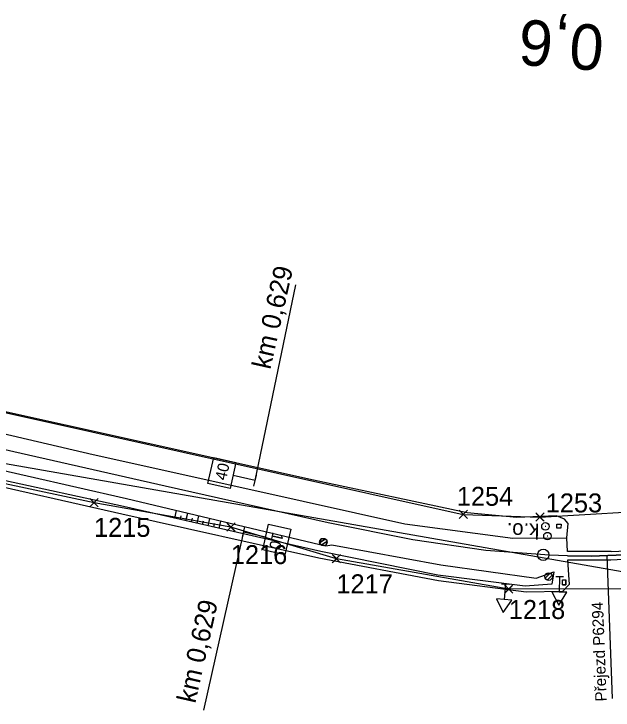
# Model space of a CAD drawing. Extents: x -738085 to -734426, y -1122197 to -1119748.
# Drawn here: x -734654.8 to -734575.8, y -1120245.5 to -1120153.7 of the extents above; entities that cross this region are included whole.
import ezdxf

# ---------------------------------------------------------------- set-up
doc = ezdxf.new("R2010")
doc.units = 0
for name, color, linetype in [('SŽDC', 7, 'Continuous'), ('Vrstva 1', 7, 'Continuous'), ('Vrstva 11', 7, 'Continuous'), ('Vrstva 12', 7, 'Continuous'), ('Vrstva 27', 7, 'Continuous'), ('Vrstva 4', 7, 'Continuous'), ('Vrstva 48', 7, 'Continuous'), ('Vrstva 49', 7, 'Continuous'), ('Vrstva 5', 7, 'Continuous'), ('Vrstva 51', 7, 'Continuous'), ('Vrstva 60', 7, 'Continuous'), ('Vrstva 63', 7, 'Continuous'), ('Vrstva 7', 7, 'Continuous')]:
    doc.layers.add(name, color=color, linetype=linetype)

msp = doc.modelspace()

# ---------------------------------------------------------------- linework, layer by layer
at = {"layer": 'SŽDC'}
for p, q in [((-734676.02, -1120201.83), (-734595.59, -1120219.69)), ((-734626.24, -1120221.38), (-734644.28, -1120218.16)), ((-734585.49, -1120220.06), (-734570.35, -1120219.16)), ((-734595.59, -1120219.69), (-734585.49, -1120220.06)), ((-734612.32, -1120225.54), (-734626.24, -1120221.38)), ((-734589.59, -1120229.56), (-734612.32, -1120225.54)), ((-734562.36, -1120229.51), (-734589.59, -1120229.56))]:
    msp.add_line(p, q, dxfattribs=at)
msp.add_lwpolyline([(-734644.28, -1120218.16), (-734672.9, -1120212.048), (-734681.74, -1120210.16)], dxfattribs=at)
at = {"layer": 'Vrstva 1'}
for points in [[(-734613.421, -1120220.79), (-734634.887, -1120215.956), (-734653.902, -1120211.657), (-734667.211, -1120208.647), (-734679.781, -1120205.8), (-734683.652, -1120204.918), (-734685.399, -1120204.523), (-734700.124, -1120201.196), (-734707.734, -1120199.476), (-734730.994, -1120194.203), (-734759.473, -1120187.753), (-734794.897, -1120179.749), (-734825.419, -1120172.844), (-734846.465, -1120168.091), (-734858.476, -1120165.343)], [(-734613.421, -1120220.79), (-734634.887, -1120215.956), (-734653.902, -1120211.657), (-734667.211, -1120208.647), (-734679.781, -1120205.8), (-734683.652, -1120204.918), (-734685.399, -1120204.523), (-734700.124, -1120201.196), (-734707.734, -1120199.476), (-734730.994, -1120194.203), (-734759.473, -1120187.753), (-734794.897, -1120179.749), (-734825.419, -1120172.844), (-734846.465, -1120168.091), (-734858.476, -1120165.343)], [(-734571.046, -1120224.919), (-734578.724, -1120225.209), (-734581.845, -1120225.143), (-734584.227, -1120225.092), (-734592.616, -1120224.456), (-734602.238, -1120223.05), (-734613.421, -1120220.79)], [(-734571.046, -1120224.919), (-734578.724, -1120225.209), (-734581.845, -1120225.143), (-734584.227, -1120225.092), (-734592.616, -1120224.456), (-734602.238, -1120223.05), (-734613.421, -1120220.79)]]:
    msp.add_lwpolyline(points, dxfattribs=at)
at = {"layer": 'Vrstva 11'}
for p, q in [((-734613.741, -1120222.96), (-734614.524, -1120223.455)), ((-734613.547, -1120223.281), (-734614.319, -1120223.769)), ((-734584.129, -1120227.449), (-734584.798, -1120228.09)), ((-734583.875, -1120227.725), (-734584.535, -1120228.357))]:
    msp.add_line(p, q, dxfattribs=at)
for centre in [(-734614.037, -1120223.359), (-734584.34, -1120227.899)]:
    msp.add_circle(centre, 0.5, dxfattribs=at)
at = {"layer": 'Vrstva 12'}
for p, q in [((-734613.724, -1120223.83), (-734614.508, -1120223.672)), ((-734582.533, -1120228.971), (-734582.083, -1120228.971))]:
    msp.add_line(p, q, dxfattribs=at)
for points in [[(-734582.722, -1120221.527), (-734583.272, -1120221.515), (-734583.26, -1120220.965), (-734582.71, -1120220.977), (-734582.722, -1120221.527)], [(-734614.35, -1120222.888), (-734613.566, -1120223.046), (-734613.724, -1120223.83), (-734614.508, -1120223.672), (-734614.35, -1120222.888)], [(-734614.35, -1120222.888), (-734614.508, -1120223.672), (-734614.508, -1120223.672)], [(-734613.566, -1120223.046), (-734613.724, -1120223.83), (-734613.724, -1120223.83)], [(-734582.533, -1120228.321), (-734582.083, -1120228.321), (-734582.083, -1120228.971), (-734582.533, -1120228.971), (-734582.533, -1120228.321)], [(-734582.533, -1120228.321), (-734582.533, -1120228.321), (-734582.083, -1120228.321), (-734582.083, -1120228.321)], [(-734582.533, -1120228.971), (-734582.533, -1120228.971), (-734582.533, -1120228.321)], [(-734582.083, -1120228.971), (-734582.083, -1120228.971), (-734582.083, -1120228.321)]]:
    msp.add_lwpolyline(points, dxfattribs=at)
at = {"layer": 'Vrstva 27'}
msp.add_line((-734584.441, -1120222.566), (-734584.541, -1120222.564), dxfattribs=at)
msp.add_circle((-734584.491, -1120222.565), 0.5, dxfattribs=at)
at = {"layer": 'Vrstva 4'}
msp.add_line((-734575.9, -1120244.003), (-734576.613, -1120225.129), dxfattribs=at)
for points in [[(-734685.169, -1120203.528), (-734684.555, -1120202.999), (-734671.173, -1120205.544), (-734644.385, -1120211.815), (-734623.222, -1120216.49), (-734603.28, -1120220.93), (-734589.054, -1120222.819), (-734581.933, -1120222.775)], [(-734581.845, -1120225.143), (-734578.724, -1120225.209), (-734571.046, -1120224.919)]]:
    msp.add_lwpolyline(points, dxfattribs=at)
at = {"layer": 'Vrstva 48'}
for p, q in [((-734633.619, -1120220.212), (-734633.383, -1120219.181)), ((-734632.887, -1120220.379), (-734632.77, -1120219.867)), ((-734632.156, -1120220.546), (-734631.924, -1120219.528)), ((-734631.425, -1120220.713), (-734631.31, -1120220.207)), ((-734630.694, -1120220.88), (-734630.465, -1120219.875)), ((-734629.231, -1120221.214), (-734629.005, -1120220.222)), ((-734629.963, -1120221.047), (-734629.849, -1120220.548)), ((-734628.5, -1120221.381), (-734628.388, -1120220.888)), ((-734627.769, -1120221.548), (-734627.546, -1120220.57))]:
    msp.add_line(p, q, dxfattribs=at)
at = {"layer": 'Vrstva 49'}
for p, q in [((-734640.39, -1120218.667), (-734667.641, -1120212.759)), ((-734614.356, -1120224.609), (-734640.39, -1120218.667)), ((-734598.954, -1120227.698), (-734614.356, -1120224.609)), ((-734587.437, -1120229.178), (-734598.954, -1120227.698))]:
    msp.add_line(p, q, dxfattribs=at)
for points in [[(-734683.53, -1120207.371), (-734683.499, -1120207.692), (-734668.248, -1120211.532), (-734667.467, -1120211.708), (-734666.214, -1120211.637), (-734640.018, -1120217.602), (-734614.508, -1120223.672), (-734613.724, -1120223.83), (-734612.931, -1120223.724), (-734598.542, -1120226.335), (-734585.987, -1120228.092), (-734583.653, -1120227.271)], [(-734583.653, -1120227.271), (-734583.922, -1120228.893), (-734587.437, -1120229.178)]]:
    msp.add_lwpolyline(points, dxfattribs=at)
at = {"layer": 'Vrstva 5'}
for p, q in [((-734623.023, -1120215.234), (-734617.67, -1120189.43)), ((-734623.023, -1120215.234), (-734625.95, -1120214.575)), ((-734623.188, -1120215.966), (-734622.858, -1120214.502)), ((-734624.584, -1120222.019), (-734629.86, -1120245.51)), ((-734624.419, -1120221.287), (-734624.749, -1120222.751)), ((-734624.584, -1120222.019), (-734621.657, -1120222.678))]:
    msp.add_line(p, q, dxfattribs=at)
for points in [[(-734625.565, -1120212.868), (-734626.334, -1120216.282), (-734629.261, -1120215.623), (-734628.492, -1120212.209)], [(-734622.042, -1120224.385), (-734621.273, -1120220.971), (-734618.346, -1120221.63), (-734619.115, -1120225.044)]]:
    msp.add_lwpolyline(points, close=True, dxfattribs=at)
at = {"layer": 'Vrstva 51'}
for p, q in [((-734576.111, -1120224.576), (-734581.836, -1120224.609)), ((-734570.996, -1120225.49), (-734576.137, -1120225.727)), ((-734582.395, -1120227.955), (-734583.395, -1120227.933)), ((-734589.549, -1120228.959), (-734590.547, -1120228.883))]:
    msp.add_line(p, q, dxfattribs=at)
for points in [[(-734581.836, -1120224.609), (-734581.933, -1120222.775), (-734581.75, -1120220.917), (-734582.259, -1120220.314), (-734583.293, -1120219.898), (-734588.526, -1120220.107), (-734595.069, -1120219.502), (-734615.337, -1120215.17), (-734658.976, -1120205.526)], [(-734576.137, -1120225.727), (-734581.854, -1120225.721), (-734581.624, -1120228.938), (-734582.53, -1120229.883), (-734587.309, -1120229.935), (-734598.842, -1120228.47), (-734614.658, -1120225.477), (-734640.597, -1120219.657), (-734660.828, -1120215.105)], [(-734576.111, -1120224.576), (-734571.095, -1120224.355), (-734571.677, -1120222.937), (-734572.567, -1120221.675), (-734572.658, -1120219.943)], [(-734582.895, -1120227.944), (-734582.938, -1120229.944), (-734583.937, -1120229.922), (-734582.975, -1120231.693), (-734581.938, -1120229.965), (-734582.938, -1120229.944)], [(-734590.048, -1120228.921), (-734590.199, -1120230.915), (-734591.196, -1120230.84), (-734590.331, -1120232.66), (-734589.202, -1120230.991), (-734590.199, -1120230.915)]]:
    msp.add_lwpolyline(points, dxfattribs=at)
at = {"layer": 'Vrstva 60'}
for p, q in [((-734643.83, -1120218.61), (-734644.83, -1120217.61)), ((-734643.83, -1120217.71), (-734644.83, -1120218.71)), ((-734644.73, -1120218.61), (-734643.73, -1120217.61)), ((-734644.73, -1120217.71), (-734643.73, -1120218.71)), ((-734644.28, -1120218.16), (-734644.28, -1120218.16)), ((-734595.14, -1120220.14), (-734596.14, -1120219.14)), ((-734595.14, -1120219.24), (-734596.14, -1120220.24)), ((-734596.04, -1120220.14), (-734595.04, -1120219.14)), ((-734596.04, -1120219.24), (-734595.04, -1120220.24)), ((-734595.59, -1120219.69), (-734595.59, -1120219.69)), ((-734585.04, -1120220.51), (-734586.04, -1120219.51)), ((-734585.04, -1120219.61), (-734586.04, -1120220.61)), ((-734585.94, -1120220.51), (-734584.94, -1120219.51)), ((-734585.94, -1120219.61), (-734584.94, -1120220.61)), ((-734585.49, -1120220.06), (-734585.49, -1120220.06)), ((-734625.79, -1120221.83), (-734626.79, -1120220.83)), ((-734625.79, -1120220.93), (-734626.79, -1120221.93)), ((-734626.69, -1120221.83), (-734625.69, -1120220.83)), ((-734626.69, -1120220.93), (-734625.69, -1120221.93)), ((-734626.24, -1120221.38), (-734626.24, -1120221.38)), ((-734611.87, -1120225.99), (-734612.87, -1120224.99)), ((-734611.87, -1120225.09), (-734612.87, -1120226.09)), ((-734612.77, -1120225.99), (-734611.77, -1120224.99)), ((-734612.77, -1120225.09), (-734611.77, -1120226.09)), ((-734612.32, -1120225.54), (-734612.32, -1120225.54)), ((-734589.14, -1120230.01), (-734590.14, -1120229.01)), ((-734589.14, -1120229.11), (-734590.14, -1120230.11)), ((-734590.04, -1120230.01), (-734589.04, -1120229.01)), ((-734590.04, -1120229.11), (-734589.04, -1120230.11)), ((-734589.59, -1120229.56), (-734589.59, -1120229.56))]:
    msp.add_line(p, q, dxfattribs=at)
at = {"layer": 'Vrstva 63'}
msp.add_line((-734667.467, -1120210.987), (-734562.448, -1120229.372), dxfattribs=at)
at = {"layer": 'Vrstva 7'}
msp.add_line((-734584.709, -1120221.28), (-734584.809, -1120221.278), dxfattribs=at)
for centre, radius in [((-734584.759, -1120221.279), 0.5), ((-734585.043, -1120225.03), 0.75), ((-734585.043, -1120225.03), 0.75)]:
    msp.add_circle(centre, radius, dxfattribs=at)

# ---------------------------------------------------------------- texts
at = {"layer": 'Vrstva 27'}
msp.add_text('k.o.', height=2, rotation=178.78201, dxfattribs=at).set_placement((-734585.55, -1120220.92))
at = {"layer": 'Vrstva 4'}
msp.add_text('Přejezd P6294', height=1.5, rotation=92.16305, dxfattribs=at).set_placement((-734576.68, -1120244.35))
at = {"layer": 'Vrstva 5'}
for s, height, rotation, p in [('km 0,629', 2.5, 77.30907, (-734621.04, -1120200.67)), ('40', 1.5, 77.30907, (-734626.882, -1120215.301)), ('10', 1.5, 257.30907, (-734620.725, -1120221.952)), ('km 0,629', 2.5, 77.34161, (-734630.94, -1120244.71))]:
    msp.add_text(s, height=height, rotation=rotation, dxfattribs=at).set_placement(p)
at = {"layer": 'Vrstva 60'}
for s, p in [('1254', (-734596.444, -1120218.563)), ('1253', (-734584.724, -1120219.435)), ('1215', (-734644.28, -1120222.658)), ('1216', (-734626.24, -1120226.254)), ('1217', (-734612.32, -1120230.104)), ('1218', (-734589.59, -1120233.493))]:
    msp.add_text(s, height=2.5, dxfattribs=at).set_placement(p)
at = {"layer": 'Vrstva 7'}
msp.add_text('0,6', height=6, rotation=175.6645, dxfattribs=at).set_placement((-734576.881, -1120155.22))
msp.add_text('0,6', height=6, rotation=175.6645, dxfattribs=at).set_placement((-734576.881, -1120155.22))

doc.saveas('drawing.dxf')
